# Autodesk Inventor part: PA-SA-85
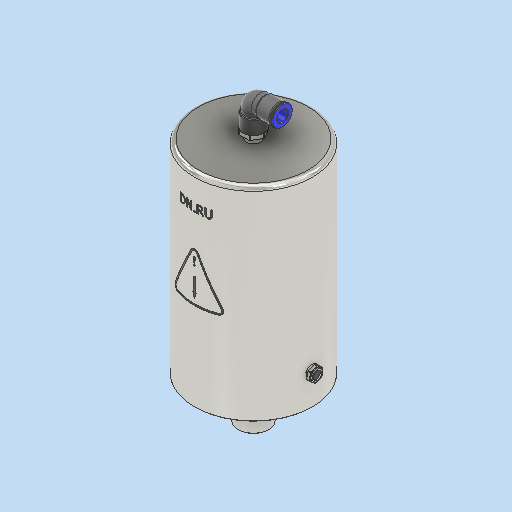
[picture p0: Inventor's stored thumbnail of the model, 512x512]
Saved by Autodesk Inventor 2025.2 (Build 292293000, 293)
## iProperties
Created: 2024-12
Part Number: PA-SA-85
Material: Типовые
Document SubType Name: Modeling
Designer: DN.RU
Density: 3.64653 g/cm^3
Appearance: По умолчанию
Description: D290-00344
Mass: 3090 g
Surface Area: 625.481 cm^2
Volume: 847.38 cm^3
Sending System: Autodesk Inventor 2025
Preprocessor: ST-DEVELOPER v20
Title: Пневмопривод с возвратными пружинами DN.ru
Author: DN.RU
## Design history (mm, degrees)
feature "Твердое тело1"
sketch "Эскиз1"
  geometry: C1 r 7 at (0, -3.994) reference; 1 further point
extrude "Выдавливание1" join sketch "Эскиз1" distance "d0" = 10; taper "d1" = 0 deg
node "Непосредственное редактирование1"
sketch "Эскиз2"
  geometry: L1 (-7.071, 0)-(0, 7.071); L2 (0, 7.071)-(7.071, 0); L3 (7.071, 0)-(0, -7.071); L4 (0, -7.071)-(-7.071, 0); L5 (-7.071, 0)-(7.071, 0); L6 (0, 7.071)-(0, -7.071); L7 (-7.071, 0)-(2.929, 0); C1 r 8.5 at (0, 0); 1 further point
  constraints: 14 end point, 2 midpoint, 2 parallel, 1 centre point, 1 coincident, 1 equal length, 1 horizontal, 1 perpendicular
  dimensions: "d5" = 10 distance of L1.start L1.end; "d6" = 45 deg angle of L7 L1; "d7" = 10 distance of L1.end L2.end; "d8" = 17 diameter of C1
extrude "Выдавливание2" join sketch "Эскиз2" distance "d9" = 16; taper "d10" = 0 deg
sketch "Эскиз3"
  geometry: C1 r 42.5 at (0, 0) reference; 1 further point
extrude "Выдавливание3" join sketch "Эскиз3" stored distance "d11" = 10; taper "d12" = 0 deg
node "Непосредственное редактирование2"
sketch "Эскиз4"
  geometry: C1 r 42.5 at (9.705, -41.274) reference; 1 further point
extrude "Выдавливание4" join sketch "Эскиз4" distance "d16" = 10; taper "d17" = 0 deg
sketch "Эскиз5"
  geometry: C1 r 11 at (0, 0) reference; C2 r 13 at (0, 0); 1 further point
  constraints: 1 centre point
  dimensions: "d19" = 2 radial gap between concentric circles of C1 C2
extrude "Выдавливание5" join sketch "Эскиз5" distance "d20" = 20; taper "d21" = 0 deg
chamfer "Фаска1" distance "d22" = 2; stored, may be unused: second distance "d23" = 2, angle "d24" = 45 deg
fillet "Сопряжение1" dims "d25" = 3
node "РабПлоскость1"
sketch "Эскиз6"
  geometry: L1 (-12.672, 51.233)-(-0.411, 51.233); L2 (-0.411, 51.233)-(-0.411, 48.121); L3 (-0.411, 48.121)-(-12.672, 48.121); L4 (-12.672, 48.121)-(-12.672, 51.233); L5 (1.758, 19.98)-(16.115, -9.265); L6 (14.319, -12.146)-(-15.009, -12.146); L7 (-16.789, -9.234)-(-1.818, 20.01); L8 (17.012, -8.824)-(2.656, 20.421); L9 (-2.708, 20.466)-(-17.68, -8.779); L10 (-15.009, -13.146)-(14.319, -13.146); L11 (-1.47, 17.4)-(1.268, 17.4); L12 (1.268, 17.4)-(1.268, 11.4); L13 (1.268, 11.4)-(-1.47, 11.4); L14 (-1.47, 11.4)-(-1.47, 17.4); L15 (-0.5, -5)-(-0.5, 5); L16 (-0.5, 5)-(0.5, 5); L17 (0.5, 5)-(0.5, -5); L18 (0.5, -5)-(-0.5, -5); L19 (-0.5, -5)-(0.5, 5); L20 (-0.5, 5)-(0.5, -5); L21 (0, -5)-(0, -8.824); L22 (0, -8.824)-(1.293, -4.923); L23 (1.293, -4.923)-(-1.269, -4.923); L24 (-1.269, -4.923)-(0, -8.824); A1 r 2 centre (-15.009, -10.146) between (-16.789, -9.234) and (-15.009, -12.146); A2 r 2 centre (-0.037, 19.099) between (1.758, 19.98) and (-1.818, 20.01); A3 r 2 centre (14.319, -10.146) between (14.319, -12.146) and (16.115, -9.265); A4 r 3 centre (-0.037, 19.099) between (2.656, 20.421) and (-2.708, 20.466); A5 r 3 centre (-15.009, -10.146) between (-17.68, -8.779) and (-15.009, -13.146); A6 r 3 centre (14.319, -10.146) between (14.319, -13.146) and (17.012, -8.824); 2 further points
  constraints: 32 end point, 12 point on circle, 6 centre point, 6 tangent, 3 midpoint, 2 equal radius, 2 parallel, 2 perpendicular, 2 vertical, 1 coincident, 1 horizontal, 9 other
  dimensions: "d27" = 2 radius of A1 (derived); "d28" = 1 distance between parallel lines of L5 L8; "d29" = 10 distance of L15.start L15.end; "d30" = 1 distance of L15.end L16.end
feature "Рельеф1" sketch "Эскиз6" dims "d31" = 0.1, "d32" = 0
node "Непосредственное редактирование3"
node "Твердое тело2"
feature "Размер1" dims "d2" = -5
feature "Размер2" dims "d3" = 2
feature "Размер3" dims "d4" = -2
feature "Перенос1" dims "d15" = 4.3
feature "Размер4" dims "d18" = 15
feature "Перенос2" dims "d47" = 7
other parameters: "d13" = 0, "d14" = 0, "d45" = 0, "d46" = 0
